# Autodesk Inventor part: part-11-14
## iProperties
Company: CADCIM Technologies
Shininess: 64.0
Length Units: 11269
Angle Units: 11279
Time Units: 11290
Mass Units: 11283
Length Display Precision: 3
Angle Display Precision: 2
Compacted: True
Part Number: part-11-14
Document SubType Name: Modeling
Created: 2002-12
Designer: deepak
Description: Sample Drawing
Engineer: Deepak
Vendor: CADSoft
Density: 1 g/cm^3
Density: 0.0
Volumn: 0.0
Area: 0.0
PropertySet Name: Model Information
Control State: 0
Master: False
Checked Out: False
Author: deepak
Title: Aligned Section
Revision Number: 4
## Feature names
1. Revolution1
2. Hole1
3. Extrusion1
4. Hole2
5. Circular Pattern1
